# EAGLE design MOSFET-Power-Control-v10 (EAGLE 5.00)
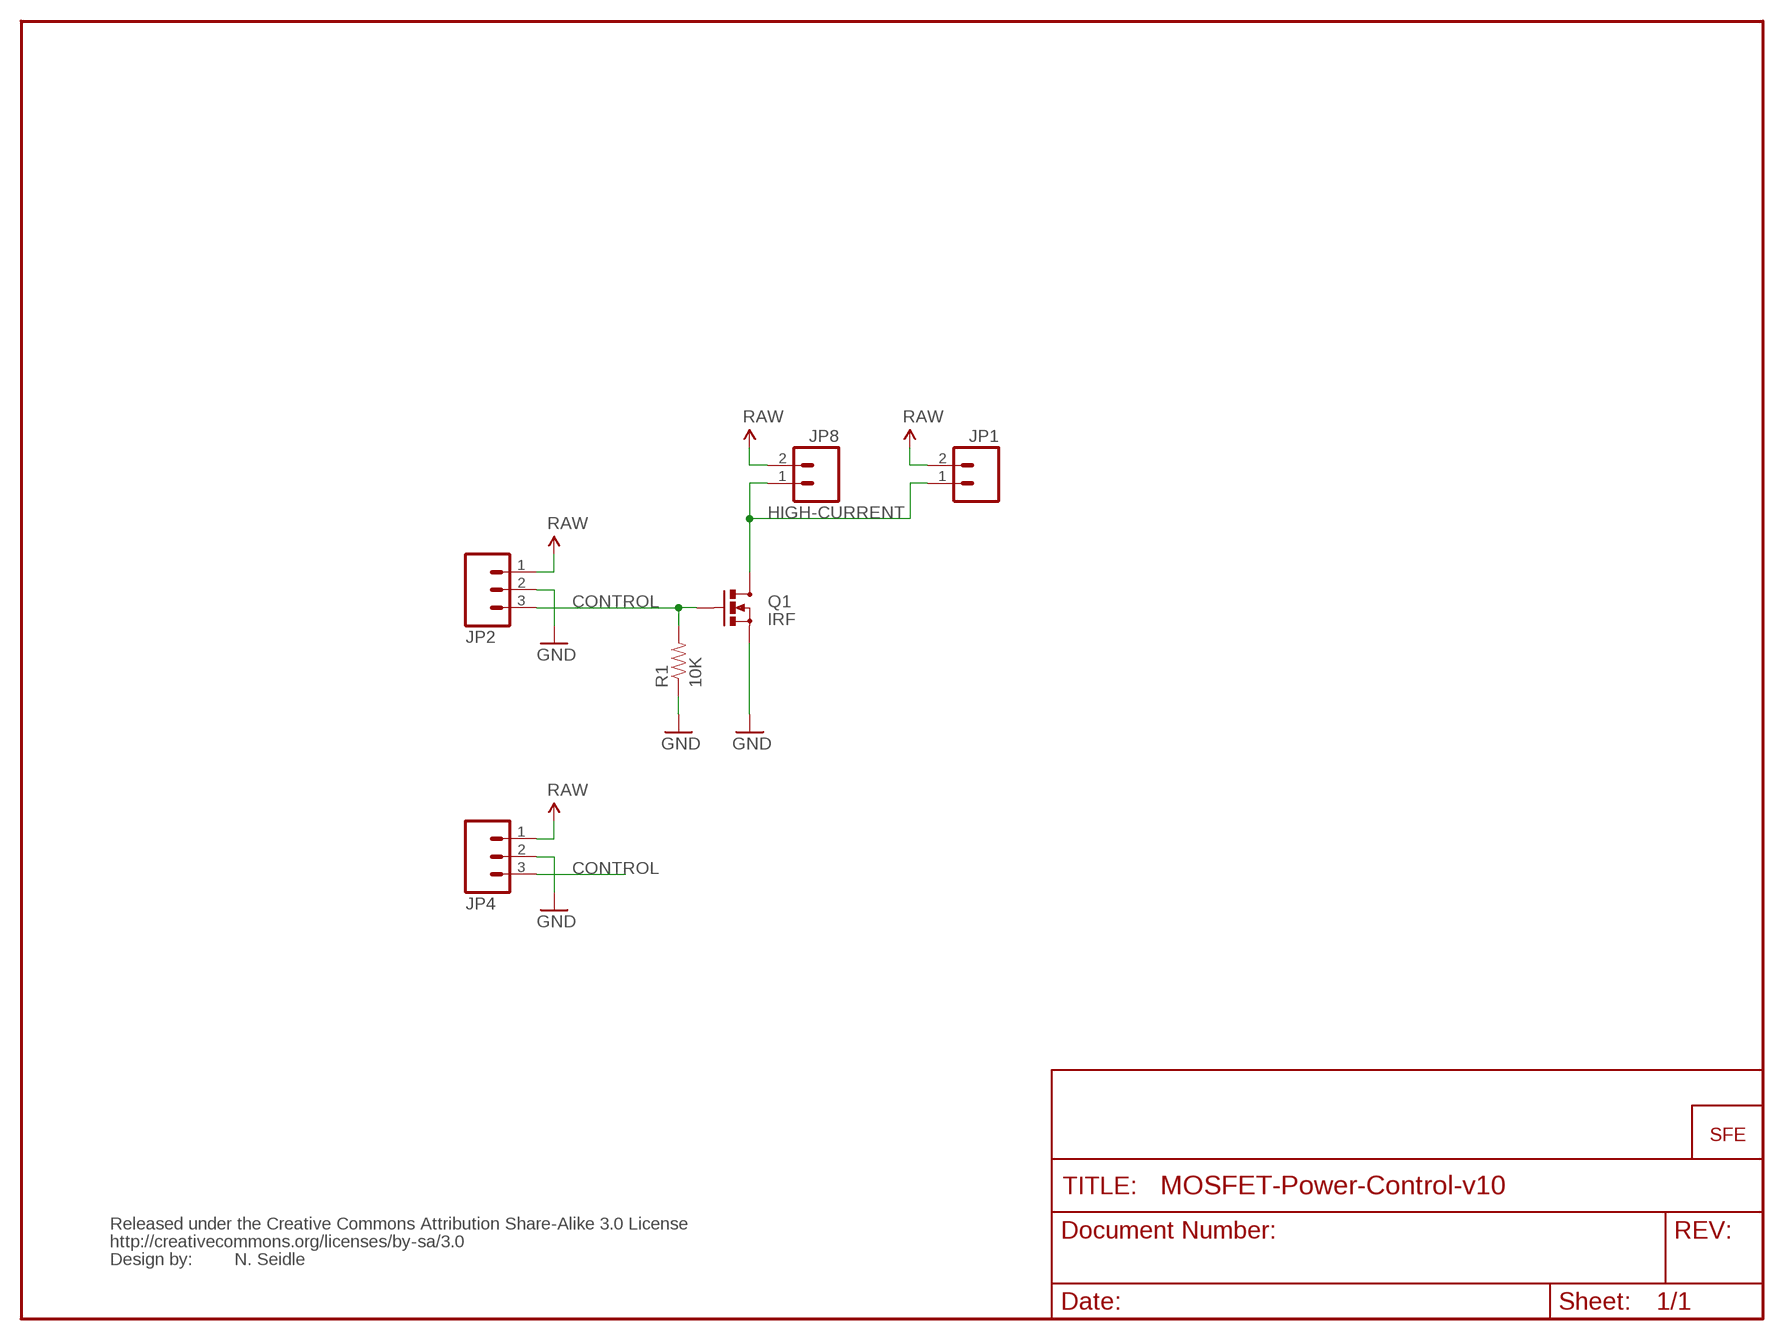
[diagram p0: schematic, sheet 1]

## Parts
JP1  M023.5MM  [SCREWTERMINAL-3.5MM-2]
JP2  M03JST-PTH  [JST-3-PTH]
JP4  M03SCREW  [SCREWTERMINAL-3.5MM-3]
JP7  LOGO-SFESK  [SFE-LOGO-FLAME]
JP8  M02JST-PTH-2  [JST-2-PTH]
Q1  IRF  MOSFET-NCHANNELPTH2  [TO220V]
R1  10K  RESISTORPTH1  [AXIAL-0.3]
U$1  CREATIVE_COMMONS  [CREATIVE_COMMONS]

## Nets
CONTROL: JP2.3 JP4.3 Q1.1(G) R1.P$2
GND: JP2.2 JP4.2 Q1.3(S) R1.P$1
HIGH-CURRENT: JP1.1 JP8.1 Q1.2(D)
VCC: JP1.2 JP2.1 JP4.1 JP8.2 ; supply symbol labelled RAW

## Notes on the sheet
- N. Seidle

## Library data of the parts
JP1 JP8 = SparkFun:M02: Header 2
JP2 JP4 = SparkFun:M03: Header 3 Standard 3-pin 0.1" header. Use with straight break away headers (SKU : PRT-00116), right angle break away headers (PRT-00553), swiss pins (PRT-00743), machine pins (PRT-00117), and female headers (PRT-00115). Molex polarized connector foot print use with SKU : PRT-08232 with associated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
JP7 = SparkFun:LOGO-SFE: Spark Fun Electronics PCB Logo
Q1 = SparkFun:MOSFET-NCHANNEL
R1 = SparkFun:RESISTOR: Resistor
U$1 = SparkFun:CREATIVE_COMMONS

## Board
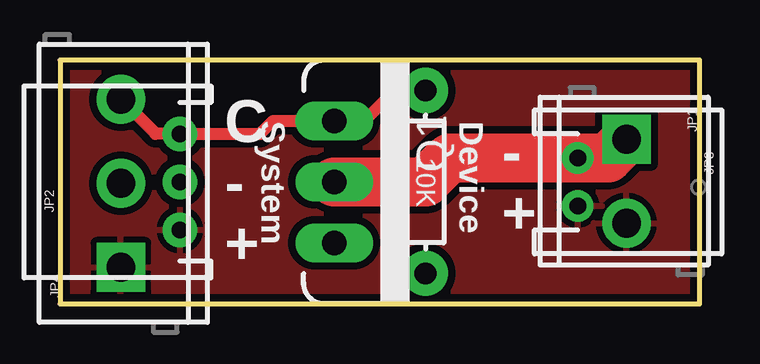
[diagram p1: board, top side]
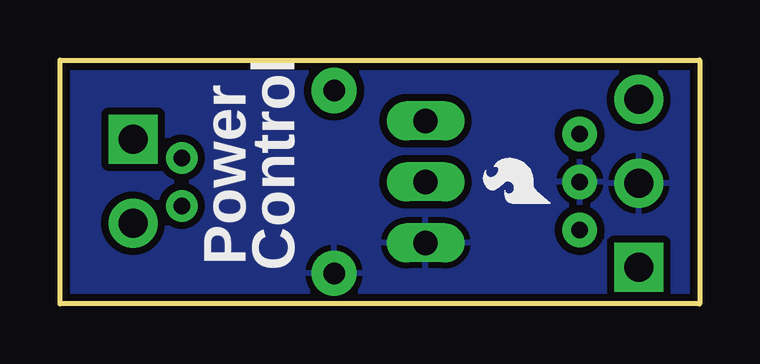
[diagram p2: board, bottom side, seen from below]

Size 26.67 x 10.16 mm. Coordinates in mm from the lower left corner, seen from the top.
Outline: 0,0 26.67,0 26.67,10.16 0,10.16 0,0
Copper layers (1*16): Top 0.035mm / dielectric 1.5mm / Bottom 0.035mm
Design rules "SparkFun": minimum track width 8mil, minimum drill 20mil, track to track 8mil, track to pad 8mil, pad to pad 8mil, via to via 8mil, smd to smd 8mil, copper to edge 10mil, drill to drill 8mil, minimum pad ring 12mil, minimum via ring 10mil, stop-mask expansion 4mil, vias tented up to drill 20mil, thermal gap 10mil

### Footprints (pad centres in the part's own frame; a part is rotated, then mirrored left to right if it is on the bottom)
SCREWTERMINAL-3.5MM-2 = drill 1.2 pad 2.032 square: 1 0,0 | drill 1.2 pad 2.032 round: 2 3.5,0
JST-3-PTH = drill 0.7 pad 1.448 round: 1 -2,-5; 2 0,-5; 3 2,-5
SCREWTERMINAL-3.5MM-3 = drill 1.2 pad 2.032 square: 1 0,0 | drill 1.2 pad 2.032 round: 2 3.5,0; 3 7,0
JST-2-PTH = drill 0.7 round: 1 -1,0; 2 1,0
TO220V = drill 1.016 long: 1 -2.54,0; 2 0,0; 3 2.54,0
AXIAL-0.3 = drill 0.9 pad 1.88 round: P$1 -3.81,0; P$2 3.81,0

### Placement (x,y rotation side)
JP1  23.62,6.86 270 top
JP2  0,5.08 90 top
JP4  2.54,1.52 90 top
JP7  6.22,4.19 90 bottom
JP8  21.59,5.08 270 top
Q1  11.43,5.08 270 top
R1  15.24,5.08 90 top
U$1  not placed on the board

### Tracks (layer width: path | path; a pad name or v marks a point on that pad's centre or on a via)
CONTROL
  Top 0.508: R1.P$2 13.97,8.89 12.7,7.62 Q1.1 8.89,7.62 8.35,7.08 JP2.3 3.98,7.08 JP4.3
GND
  pour Bottom (isolate 0.305): 0,10.16 26.67,10.16 26.67,0 0,0
HIGH-CURRENT
  Top 2.032: Q1.2 15.24,5.08 16.24,6.08 JP8.1 22.84,6.08 JP1.1
VCC
  pour Top (isolate 0.305): 0,10.16 26.67,10.16 26.67,0 0,0

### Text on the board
tPlace: System | Device | C | - | - | + | +
bPlace: Control | Power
